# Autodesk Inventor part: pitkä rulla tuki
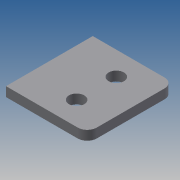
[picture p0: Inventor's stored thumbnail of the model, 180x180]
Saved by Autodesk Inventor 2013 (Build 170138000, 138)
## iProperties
Created: 2013-08
Part Number: pitkä rulla tuki
Material: Generic
Document SubType Name: Sheet Metal
Designer: Reko Tuppurainen
Density: 1 g/cm^3
Sheet Metal Rule: Default_mm
Author: Reko Tuppurainen
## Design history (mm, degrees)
node "Face1"
  sketch "Sketch1"
    geometry: L1 (-11.115, 4.26)-(57.885, 4.26); L2 (57.885, 4.26)-(57.885, -69.44); L3 (57.885, -69.44)-(-11.115, -69.44); L4 (-11.115, -69.44)-(-11.115, 4.26); 1 further point
    constraints: 8 end point, 2 parallel, 1 horizontal, 1 perpendicular
    dimensions: "d0" = 69 distance of L2.end L3.end; "d1" = 73.7 distance of L1.end L2.end
feature "Corner Round1" dims "d3" = 8
sketch "Sketch2"
  geometry: L1 (-11.115, 4.26)-(49.885, 4.26) reference; L2 (-11.115, -69.44)-(-11.115, 4.26) reference; L3 (49.885, -69.44)-(-11.115, -69.44) reference; C1 r 6.5 at (28.885, -15.74); C2 r 6.5 at (28.885, -49.44); 1 further point
  constraints: 2 centre point
  dimensions: "d4" = 13 diameter of C1; "d5" = 13 diameter of C2; "d6" = 20 distance from line of L1 C1.centre; "d7" = 20 distance from line of L3 C2.centre; "d8" = 40 distance from line of L2 C1.centre; "d9" = 40 distance from line of L2 C2.centre
cut "Cut1" sketch "Sketch2" dims "d10" = 8 (= Thickness), "d11" = 0
body "Solid1"
face "Plate1" dims "Thickness" = 8 (derived)
other parameters: "BendRadius" = 8 (= Thickness), "BendReliefWidth" = 8 (= Thickness), "BendReliefDepth" = 4 (= 0.5 x Thickness), "CornerReliefSize" = 32 (= 4 x Thickness), "SeamGap" = 0.01, "MinimumRemnant" = 16 (= 2 x Thickness), "TransitionRadius" = 8 (= BendRadius), "JacobiRadiusSize" = 8 (= BendRadius), "GapSize" = 8 (= Thickness), "d2" = 8 (= BendRadius)
